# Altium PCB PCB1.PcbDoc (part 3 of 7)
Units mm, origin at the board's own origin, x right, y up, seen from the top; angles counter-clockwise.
Board outline 139.9 x 46.81 mm, 2 copper layers (Top Layer, Bottom Layer); 0 components, 100 nets, 100 pads, 0 vias.
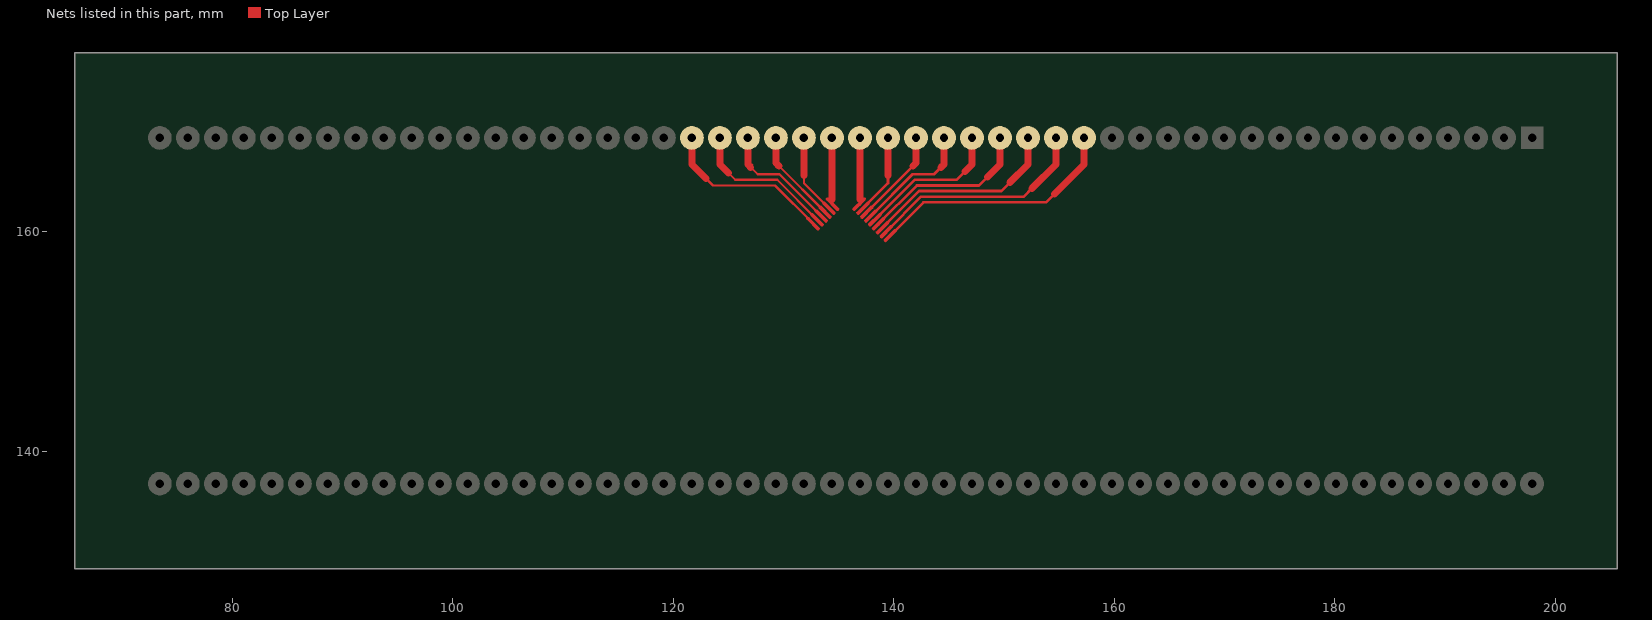
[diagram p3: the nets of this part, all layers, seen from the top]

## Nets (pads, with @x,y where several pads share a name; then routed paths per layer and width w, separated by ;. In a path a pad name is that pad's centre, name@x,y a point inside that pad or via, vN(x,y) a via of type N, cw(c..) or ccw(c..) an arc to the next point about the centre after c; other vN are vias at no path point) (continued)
$Net29: pad.1@121.687,168.455 | length 39.5
  Top Layer w0.03: 132.119,161.129 132.388,161.129 ; 132.121,161.114 132.403,161.114 ; 132.124,161.099 132.419,161.099 ; 132.132,161.084 132.434,161.084 ; 132.134,161.175 132.342,161.175 ; 132.144,161.068 132.449,161.068 ; 132.16,161.053 132.464,161.053 ; 132.16,161.206 132.312,161.206 ; 132.175,161.038 132.48,161.038 ; 132.177,161.221 132.297,161.221 ; 132.19,161.023 132.495,161.023 ; 132.2,161.236 132.274,161.236 ; 132.205,161.007 132.51,161.007 ; 132.22,160.992 132.525,160.992 ; 132.236,160.977 132.541,160.977 ; 132.251,160.962 132.556,160.962 ; 132.266,160.947 132.571,160.947 ; 132.281,160.931 132.586,160.931 ; 132.297,160.916 132.601,160.916 ; 132.312,160.901 132.617,160.901 ; 132.327,160.886 132.632,160.886 ; 132.327,161.19 132.144,161.19 ; 132.342,160.87 132.647,160.87 ; 132.358,160.855 132.662,160.855 ; 132.358,161.16 132.124,161.16 ; 132.373,160.84 132.678,160.84 ; 132.373,161.145 132.119,161.145 ; 132.388,160.825 132.693,160.825 ; 132.403,160.809 132.708,160.809 ; 132.419,160.794 132.723,160.794 ; 132.434,160.779 132.739,160.779 ; 132.449,160.764 132.754,160.764 ; 132.464,160.748 132.769,160.748 ; 132.48,160.733 132.782,160.733 ; 132.495,160.718 132.797,160.718 ; 132.51,160.703 132.812,160.703 ; 132.525,160.687 132.828,160.687 ; 132.541,160.672 132.843,160.672 ; 132.556,160.657 132.858,160.657 ; 132.571,160.642 132.873,160.642 ; 132.586,160.626 132.888,160.626 ; 132.601,160.611 132.904,160.611 ; 132.614,160.596 132.919,160.596 ; 132.629,160.581 132.934,160.581 ; 132.645,160.566 132.949,160.566 ; 132.66,160.55 132.965,160.55 ; 132.675,160.535 132.98,160.535 ; 132.69,160.52 132.995,160.52 ; 132.706,160.505 133.01,160.505 ; 132.721,160.489 133.026,160.489 ; 132.736,160.474 133.041,160.474 ; 132.751,160.459 133.056,160.459 ; 132.767,160.444 133.071,160.444 ; 132.782,160.428 133.087,160.428 ; 132.797,160.413 133.102,160.413 ; 132.812,160.398 133.117,160.398 ; 132.828,160.383 133.132,160.383 ; 132.843,160.367 133.148,160.367 ; 132.858,160.352 133.163,160.352 ; 132.873,160.337 133.178,160.337 ; 132.888,160.322 133.193,160.322 ; 132.904,160.306 133.209,160.306 ; 132.919,160.291 133.224,160.291 ; 132.934,160.276 133.239,160.276 ; 132.949,160.261 133.247,160.261 ; 132.965,160.245 133.252,160.245 ; 132.98,160.23 133.254,160.23 ; 132.995,160.215 133.254,160.215 ; 133.01,160.2 133.249,160.2 ; 133.026,160.185 133.242,160.185 ; 133.041,160.169 133.231,160.169 ; 133.056,160.154 133.216,160.154 ; 133.071,160.139 133.201,160.139 ; 133.181,160.124 133.087,160.124 ; 132.119,161.145 132.124,161.16 ; 132.119,161.145 132.116,161.127 132.124,161.094 132.132,161.081 133.074,160.134 133.087,160.124 ; 132.124,161.16 132.144,161.19 ; 132.144,161.19 132.172,161.218 132.203,161.239 132.218,161.244 132.236,161.246 132.269,161.239 132.284,161.231 132.297,161.221 ; 132.297,161.221 133.239,160.273 133.247,160.261 ; 133.087,160.124 133.102,160.116 133.135,160.108 133.153,160.111 133.168,160.116 133.198,160.136 133.226,160.164 133.247,160.195 133.252,160.21 133.254,160.228 133.247,160.261
  Top Layer w0.203: 122.957,164.772 123.592,164.137 129.226,164.137 132.685,160.677
  Top Layer w0.635: pad.1@121.687,168.455 121.687,166.042 122.957,164.772
$Net30: pad.1@124.227,168.455 | length 37.2
  Top Layer w0.03: 132.472,161.482 132.741,161.482 ; 132.474,161.467 132.756,161.467 ; 132.477,161.452 132.772,161.452 ; 132.485,161.437 132.787,161.437 ; 132.487,161.528 132.695,161.528 ; 132.497,161.421 132.802,161.421 ; 132.513,161.406 132.817,161.406 ; 132.513,161.559 132.665,161.559 ; 132.528,161.391 132.833,161.391 ; 132.53,161.574 132.65,161.574 ; 132.543,161.376 132.848,161.376 ; 132.553,161.589 132.627,161.589 ; 132.558,161.361 132.863,161.361 ; 132.574,161.345 132.878,161.345 ; 132.589,161.33 132.894,161.33 ; 132.604,161.315 132.909,161.315 ; 132.619,161.3 132.924,161.3 ; 132.634,161.284 132.939,161.284 ; 132.65,161.269 132.955,161.269 ; 132.665,161.254 132.97,161.254 ; 132.68,161.239 132.985,161.239 ; 132.68,161.543 132.497,161.543 ; 132.695,161.223 133,161.223 ; 132.711,161.208 133.015,161.208 ; 132.711,161.513 132.477,161.513 ; 132.726,161.193 133.031,161.193 ; 132.726,161.498 132.472,161.498 ; 132.741,161.178 133.046,161.178 ; 132.756,161.162 133.061,161.162 ; 132.772,161.147 133.076,161.147 ; 132.787,161.132 133.092,161.132 ; 132.802,161.117 133.107,161.117 ; 132.817,161.101 133.122,161.101 ; 132.833,161.086 133.135,161.086 ; 132.848,161.071 133.15,161.071 ; 132.863,161.056 133.165,161.056 ; 132.878,161.04 133.181,161.04 ; 132.894,161.025 133.196,161.025 ; 132.909,161.01 133.211,161.01 ; 132.924,160.995 133.226,160.995 ; 132.939,160.98 133.242,160.98 ; 132.955,160.964 133.257,160.964 ; 132.967,160.949 133.272,160.949 ; 132.982,160.934 133.287,160.934 ; 132.998,160.919 133.303,160.919 ; 133.013,160.903 133.318,160.903 ; 133.028,160.888 133.333,160.888 ; 133.043,160.873 133.348,160.873 ; 133.059,160.858 133.363,160.858 ; 133.074,160.842 133.379,160.842 ; 133.089,160.827 133.394,160.827 ; 133.104,160.812 133.409,160.812 ; 133.12,160.797 133.424,160.797 ; 133.135,160.781 133.44,160.781 ; 133.15,160.766 133.455,160.766 ; 133.165,160.751 133.47,160.751 ; 133.181,160.736 133.485,160.736 ; 133.196,160.72 133.501,160.72 ; 133.211,160.705 133.516,160.705 ; 133.226,160.69 133.531,160.69 ; 133.242,160.675 133.546,160.675 ; 133.257,160.659 133.562,160.659 ; 133.272,160.644 133.577,160.644 ; 133.287,160.629 133.592,160.629 ; 133.303,160.614 133.6,160.614 ; 133.318,160.599 133.605,160.599 ; 133.333,160.583 133.607,160.583 ; 133.348,160.568 133.607,160.568 ; 133.363,160.553 133.602,160.553 ; 133.379,160.538 133.595,160.538 ; 133.394,160.522 133.584,160.522 ; 133.409,160.507 133.569,160.507 ; 133.424,160.492 133.554,160.492 ; 133.534,160.477 133.44,160.477 ; 132.472,161.498 132.477,161.513 ; 132.472,161.498 132.469,161.48 132.477,161.447 132.485,161.434 133.427,160.487 133.44,160.477 ; 132.477,161.513 132.497,161.543 ; 132.497,161.543 132.525,161.571 132.556,161.592 132.571,161.597 132.589,161.599 132.622,161.592 132.637,161.584 132.65,161.574 ; 132.65,161.574 133.592,160.626 133.6,160.614 ; 133.44,160.477 133.455,160.469 133.488,160.461 133.506,160.464 133.521,160.469 133.551,160.489 133.579,160.517 133.6,160.548 133.605,160.563 133.607,160.581 133.6,160.614
  Top Layer w0.203: 124.989,165.28 125.624,164.645 129.426,164.645 133.038,161.03
  Top Layer w0.635: pad.1@124.227,168.455 124.227,166.042 124.989,165.28
$Net31: pad.1@126.767,168.455 | length 34.9
  Top Layer w0.03: 132.828,161.836 133.097,161.836 ; 132.83,161.82 133.112,161.82 ; 132.833,161.805 133.127,161.805 ; 132.84,161.79 133.142,161.79 ; 132.843,161.881 133.051,161.881 ; 132.853,161.775 133.158,161.775 ; 132.868,161.759 133.173,161.759 ; 132.868,161.912 133.021,161.912 ; 132.883,161.744 133.188,161.744 ; 132.886,161.927 133.005,161.927 ; 132.899,161.729 133.203,161.729 ; 132.909,161.942 132.982,161.942 ; 132.914,161.714 133.219,161.714 ; 132.929,161.698 133.234,161.698 ; 132.944,161.683 133.249,161.683 ; 132.96,161.668 133.264,161.668 ; 132.975,161.653 133.28,161.653 ; 132.99,161.637 133.295,161.637 ; 133.005,161.622 133.31,161.622 ; 133.021,161.607 133.325,161.607 ; 133.036,161.592 133.341,161.592 ; 133.036,161.896 132.853,161.896 ; 133.051,161.576 133.356,161.576 ; 133.066,161.561 133.371,161.561 ; 133.066,161.866 132.833,161.866 ; 133.082,161.546 133.386,161.546 ; 133.082,161.851 132.828,161.851 ; 133.097,161.531 133.402,161.531 ; 133.112,161.515 133.417,161.515 ; 133.127,161.5 133.432,161.5 ; 133.142,161.485 133.447,161.485 ; 133.158,161.47 133.463,161.47 ; 133.173,161.455 133.478,161.455 ; 133.188,161.439 133.49,161.439 ; 133.203,161.424 133.506,161.424 ; 133.219,161.409 133.521,161.409 ; 133.234,161.394 133.536,161.394 ; 133.249,161.378 133.551,161.378 ; 133.264,161.363 133.567,161.363 ; 133.28,161.348 133.582,161.348 ; 133.295,161.333 133.597,161.333 ; 133.31,161.317 133.612,161.317 ; 133.323,161.302 133.628,161.302 ; 133.338,161.287 133.643,161.287 ; 133.353,161.272 133.658,161.272 ; 133.369,161.256 133.673,161.256 ; 133.384,161.241 133.689,161.241 ; 133.399,161.226 133.704,161.226 ; 133.414,161.211 133.719,161.211 ; 133.43,161.195 133.734,161.195 ; 133.445,161.18 133.75,161.18 ; 133.46,161.165 133.765,161.165 ; 133.475,161.15 133.78,161.15 ; 133.49,161.134 133.795,161.134 ; 133.506,161.119 133.811,161.119 ; 133.521,161.104 133.826,161.104 ; 133.536,161.089 133.841,161.089 ; 133.551,161.074 133.856,161.074 ; 133.567,161.058 133.871,161.058 ; 133.582,161.043 133.887,161.043 ; 133.597,161.028 133.902,161.028 ; 133.612,161.013 133.917,161.013 ; 133.628,160.997 133.932,160.997 ; 133.643,160.982 133.948,160.982 ; 133.658,160.967 133.955,160.967 ; 133.673,160.952 133.96,160.952 ; 133.689,160.936 133.963,160.936 ; 133.704,160.921 133.963,160.921 ; 133.719,160.906 133.958,160.906 ; 133.734,160.891 133.95,160.891 ; 133.75,160.875 133.94,160.875 ; 133.765,160.86 133.925,160.86 ; 133.78,160.845 133.91,160.845 ; 133.889,160.83 133.795,160.83 ; 132.828,161.851 132.833,161.866 ; 132.828,161.851 132.825,161.833 132.833,161.8 132.84,161.787 133.783,160.84 133.795,160.83 ; 132.833,161.866 132.853,161.896 ; 132.853,161.896 132.881,161.924 132.911,161.945 132.927,161.95 132.944,161.952 132.977,161.945 132.993,161.937 133.005,161.927 ; 133.005,161.927 133.948,160.98 133.955,160.967 ; 133.795,160.83 133.811,160.822 133.844,160.814 133.861,160.817 133.877,160.822 133.907,160.842 133.935,160.87 133.955,160.901 133.96,160.916 133.963,160.934 133.955,160.967
  Top Layer w0.203: 127.021,165.788 127.656,165.153 129.625,165.153 133.394,161.383
  Top Layer w0.635: pad.1@126.767,168.455 126.767,166.042 127.021,165.788
$Net32: pad.1@129.307,168.455 | length 32.8
  Top Layer w0.03: 133.181,162.189 133.45,162.189 ; 133.183,162.173 133.465,162.173 ; 133.186,162.158 133.48,162.158 ; 133.193,162.143 133.496,162.143 ; 133.196,162.234 133.404,162.234 ; 133.206,162.128 133.511,162.128 ; 133.221,162.112 133.526,162.112 ; 133.221,162.265 133.374,162.265 ; 133.236,162.097 133.541,162.097 ; 133.239,162.28 133.358,162.28 ; 133.252,162.082 133.557,162.082 ; 133.262,162.295 133.336,162.295 ; 133.267,162.067 133.572,162.067 ; 133.282,162.051 133.587,162.051 ; 133.297,162.036 133.602,162.036 ; 133.313,162.021 133.617,162.021 ; 133.328,162.006 133.633,162.006 ; 133.343,161.99 133.648,161.99 ; 133.358,161.975 133.663,161.975 ; 133.374,161.96 133.678,161.96 ; 133.389,161.945 133.694,161.945 ; 133.389,162.25 133.206,162.25 ; 133.404,161.929 133.709,161.929 ; 133.419,161.914 133.724,161.914 ; 133.419,162.219 133.186,162.219 ; 133.435,161.899 133.739,161.899 ; 133.435,162.204 133.181,162.204 ; 133.45,161.884 133.755,161.884 ; 133.465,161.869 133.77,161.869 ; 133.48,161.853 133.785,161.853 ; 133.496,161.838 133.8,161.838 ; 133.511,161.823 133.816,161.823 ; 133.526,161.808 133.831,161.808 ; 133.541,161.792 133.844,161.792 ; 133.557,161.777 133.859,161.777 ; 133.572,161.762 133.874,161.762 ; 133.587,161.747 133.889,161.747 ; 133.602,161.731 133.904,161.731 ; 133.617,161.716 133.92,161.716 ; 133.633,161.701 133.935,161.701 ; 133.648,161.686 133.95,161.686 ; 133.663,161.67 133.965,161.67 ; 133.676,161.655 133.981,161.655 ; 133.691,161.64 133.996,161.64 ; 133.706,161.625 134.011,161.625 ; 133.722,161.609 134.026,161.609 ; 133.737,161.594 134.042,161.594 ; 133.752,161.579 134.057,161.579 ; 133.767,161.564 134.072,161.564 ; 133.783,161.548 134.087,161.548 ; 133.798,161.533 134.103,161.533 ; 133.813,161.518 134.118,161.518 ; 133.828,161.503 134.133,161.503 ; 133.844,161.488 134.148,161.488 ; 133.859,161.472 134.164,161.472 ; 133.874,161.457 134.179,161.457 ; 133.889,161.442 134.194,161.442 ; 133.904,161.427 134.209,161.427 ; 133.92,161.411 134.225,161.411 ; 133.935,161.396 134.24,161.396 ; 133.95,161.381 134.255,161.381 ; 133.965,161.366 134.27,161.366 ; 133.981,161.35 134.285,161.35 ; 133.996,161.335 134.301,161.335 ; 134.011,161.32 134.308,161.32 ; 134.026,161.305 134.313,161.305 ; 134.042,161.289 134.316,161.289 ; 134.057,161.274 134.316,161.274 ; 134.072,161.259 134.311,161.259 ; 134.087,161.244 134.303,161.244 ; 134.103,161.228 134.293,161.228 ; 134.118,161.213 134.278,161.213 ; 134.133,161.198 134.263,161.198 ; 134.242,161.183 134.148,161.183 ; 133.181,162.204 133.186,162.219 ; 133.181,162.204 133.178,162.186 133.186,162.153 133.193,162.14 134.136,161.193 134.148,161.183 ; 133.186,162.219 133.206,162.25 ; 133.206,162.25 133.234,162.277 133.264,162.298 133.28,162.303 133.297,162.305 133.33,162.298 133.346,162.29 133.358,162.28 ; 133.358,162.28 134.301,161.333 134.308,161.32 ; 134.148,161.183 134.164,161.175 134.197,161.167 134.214,161.17 134.23,161.175 134.26,161.195 134.288,161.223 134.308,161.254 134.313,161.269 134.316,161.287 134.308,161.32
  Top Layer w0.203: 129.307,166.179 129.564,165.92 133.747,161.736
  Top Layer w0.635: pad.1@129.307,168.455 129.307,166.179 129.564,165.92
$Net33: pad.1@131.847,168.455 | length 31.2
  Top Layer w0.03: 133.534,162.542 133.803,162.542 ; 133.536,162.526 133.818,162.526 ; 133.539,162.511 133.833,162.511 ; 133.546,162.496 133.849,162.496 ; 133.549,162.587 133.757,162.587 ; 133.559,162.481 133.864,162.481 ; 133.574,162.465 133.879,162.465 ; 133.574,162.618 133.727,162.618 ; 133.59,162.45 133.894,162.45 ; 133.592,162.633 133.711,162.633 ; 133.605,162.435 133.91,162.435 ; 133.615,162.648 133.689,162.648 ; 133.62,162.42 133.925,162.42 ; 133.635,162.404 133.94,162.404 ; 133.65,162.389 133.955,162.389 ; 133.666,162.374 133.971,162.374 ; 133.681,162.359 133.986,162.359 ; 133.696,162.344 134.001,162.344 ; 133.711,162.328 134.016,162.328 ; 133.727,162.313 134.031,162.313 ; 133.742,162.298 134.047,162.298 ; 133.742,162.603 133.559,162.603 ; 133.757,162.283 134.062,162.283 ; 133.772,162.267 134.077,162.267 ; 133.772,162.572 133.539,162.572 ; 133.788,162.252 134.092,162.252 ; 133.788,162.557 133.534,162.557 ; 133.803,162.237 134.108,162.237 ; 133.818,162.222 134.123,162.222 ; 133.833,162.206 134.138,162.206 ; 133.849,162.191 134.153,162.191 ; 133.864,162.176 134.169,162.176 ; 133.879,162.161 134.184,162.161 ; 133.894,162.145 134.197,162.145 ; 133.91,162.13 134.212,162.13 ; 133.925,162.115 134.227,162.115 ; 133.94,162.1 134.242,162.1 ; 133.955,162.084 134.258,162.084 ; 133.971,162.069 134.273,162.069 ; 133.986,162.054 134.288,162.054 ; 134.001,162.039 134.303,162.039 ; 134.016,162.023 134.319,162.023 ; 134.029,162.008 134.334,162.008 ; 134.044,161.993 134.349,161.993 ; 134.059,161.978 134.364,161.978 ; 134.075,161.963 134.379,161.963 ; 134.09,161.947 134.395,161.947 ; 134.105,161.932 134.41,161.932 ; 134.12,161.917 134.425,161.917 ; 134.136,161.902 134.44,161.902 ; 134.151,161.886 134.456,161.886 ; 134.166,161.871 134.471,161.871 ; 134.181,161.856 134.486,161.856 ; 134.197,161.841 134.501,161.841 ; 134.212,161.825 134.517,161.825 ; 134.227,161.81 134.532,161.81 ; 134.242,161.795 134.547,161.795 ; 134.258,161.78 134.562,161.78 ; 134.273,161.764 134.578,161.764 ; 134.288,161.749 134.593,161.749 ; 134.303,161.734 134.608,161.734 ; 134.319,161.719 134.623,161.719 ; 134.334,161.703 134.639,161.703 ; 134.349,161.688 134.654,161.688 ; 134.364,161.673 134.661,161.673 ; 134.379,161.658 134.666,161.658 ; 134.395,161.642 134.669,161.642 ; 134.41,161.627 134.669,161.627 ; 134.425,161.612 134.664,161.612 ; 134.44,161.597 134.656,161.597 ; 134.456,161.582 134.646,161.582 ; 134.471,161.566 134.631,161.566 ; 134.486,161.551 134.616,161.551 ; 134.595,161.536 134.501,161.536 ; 133.534,162.557 133.539,162.572 ; 133.534,162.557 133.531,162.539 133.539,162.506 133.546,162.493 134.489,161.546 134.501,161.536 ; 133.539,162.572 133.559,162.603 ; 133.559,162.603 133.587,162.631 133.617,162.651 133.633,162.656 133.65,162.658 133.684,162.651 133.699,162.643 133.711,162.633 ; 133.711,162.633 134.654,161.686 134.661,161.673 ; 134.501,161.536 134.517,161.528 134.55,161.521 134.567,161.523 134.583,161.528 134.613,161.548 134.641,161.576 134.661,161.607 134.666,161.622 134.669,161.64 134.661,161.673
  Top Layer w0.203: 131.847,165.026 131.847,164.345 134.1,162.09
  Top Layer w0.635: 131.847,165.026 pad.1@131.847,168.455
$Net34: pad.1@134.387,168.455 | length 30
  Top Layer w0.03: 133.887,162.897 134.156,162.897 ; 133.889,162.882 134.171,162.882 ; 133.892,162.867 134.186,162.867 ; 133.899,162.852 134.202,162.852 ; 133.902,162.943 134.11,162.943 ; 133.912,162.836 134.217,162.836 ; 133.927,162.821 134.232,162.821 ; 133.927,162.973 134.08,162.973 ; 133.943,162.806 134.247,162.806 ; 133.945,162.989 134.065,162.989 ; 133.958,162.791 134.263,162.791 ; 133.968,163.004 134.042,163.004 ; 133.973,162.775 134.278,162.775 ; 133.988,162.76 134.293,162.76 ; 134.004,162.745 134.308,162.745 ; 134.019,162.73 134.324,162.73 ; 134.034,162.714 134.339,162.714 ; 134.049,162.699 134.354,162.699 ; 134.065,162.684 134.369,162.684 ; 134.08,162.669 134.385,162.669 ; 134.095,162.653 134.4,162.653 ; 134.095,162.958 133.912,162.958 ; 134.11,162.638 134.415,162.638 ; 134.125,162.623 134.43,162.623 ; 134.125,162.928 133.892,162.928 ; 134.141,162.608 134.446,162.608 ; 134.141,162.912 133.887,162.912 ; 134.156,162.592 134.461,162.592 ; 134.171,162.577 134.476,162.577 ; 134.186,162.562 134.491,162.562 ; 134.202,162.547 134.506,162.547 ; 134.217,162.531 134.522,162.531 ; 134.232,162.516 134.537,162.516 ; 134.247,162.501 134.55,162.501 ; 134.263,162.486 134.565,162.486 ; 134.278,162.471 134.58,162.471 ; 134.293,162.455 134.595,162.455 ; 134.308,162.44 134.611,162.44 ; 134.324,162.425 134.626,162.425 ; 134.339,162.41 134.641,162.41 ; 134.354,162.394 134.656,162.394 ; 134.369,162.379 134.672,162.379 ; 134.382,162.364 134.687,162.364 ; 134.397,162.349 134.702,162.349 ; 134.412,162.333 134.717,162.333 ; 134.428,162.318 134.733,162.318 ; 134.443,162.303 134.748,162.303 ; 134.458,162.288 134.763,162.288 ; 134.473,162.272 134.778,162.272 ; 134.489,162.257 134.793,162.257 ; 134.504,162.242 134.809,162.242 ; 134.519,162.227 134.824,162.227 ; 134.534,162.211 134.839,162.211 ; 134.55,162.196 134.854,162.196 ; 134.565,162.181 134.87,162.181 ; 134.58,162.166 134.885,162.166 ; 134.595,162.15 134.9,162.15 ; 134.611,162.135 134.915,162.135 ; 134.626,162.12 134.931,162.12 ; 134.641,162.105 134.946,162.105 ; 134.656,162.09 134.961,162.09 ; 134.672,162.074 134.976,162.074 ; 134.687,162.059 134.992,162.059 ; 134.702,162.044 135.007,162.044 ; 134.717,162.029 135.014,162.029 ; 134.733,162.013 135.02,162.013 ; 134.748,161.998 135.022,161.998 ; 134.763,161.983 135.022,161.983 ; 134.778,161.968 135.017,161.968 ; 134.793,161.952 135.009,161.952 ; 134.809,161.937 134.999,161.937 ; 134.824,161.922 134.984,161.922 ; 134.839,161.907 134.969,161.907 ; 134.948,161.891 134.854,161.891 ; 133.887,162.912 133.892,162.928 ; 133.887,162.912 133.884,162.895 133.892,162.862 133.899,162.849 134.842,161.902 134.854,161.891 ; 133.892,162.928 133.912,162.958 ; 133.912,162.958 133.94,162.986 133.971,163.006 133.986,163.012 134.004,163.014 134.037,163.006 134.052,162.999 134.065,162.989 ; 134.065,162.989 135.007,162.041 135.014,162.029 ; 134.854,161.891 134.87,161.884 134.903,161.876 134.92,161.879 134.936,161.884 134.966,161.904 134.994,161.932 135.014,161.963 135.02,161.978 135.022,161.996 135.014,162.029
  Top Layer w0.203: 134.387,162.867 134.387,162.511 134.453,162.445
  Top Layer w0.635: 134.387,162.867 pad.1@134.387,168.455
$Net35: pad.1@136.927,168.455 | length 29.9
  Top Layer w0.03: 136.292,161.983 136.549,161.983 ; 136.292,161.998 136.564,161.998 ; 136.295,162.013 136.579,162.013 ; 136.297,161.968 136.533,161.968 ; 136.305,161.952 136.518,161.952 ; 136.315,161.937 136.503,161.937 ; 136.32,162.059 136.625,162.059 ; 136.328,161.922 136.488,161.922 ; 136.335,162.074 136.64,162.074 ; 136.343,161.907 136.472,161.907 ; 136.351,162.09 136.655,162.09 ; 136.366,161.891 136.455,161.891 ; 136.366,162.105 136.671,162.105 ; 136.381,162.12 136.686,162.12 ; 136.396,162.135 136.701,162.135 ; 136.411,162.15 136.716,162.15 ; 136.427,162.166 136.732,162.166 ; 136.442,162.181 136.747,162.181 ; 136.457,162.196 136.762,162.196 ; 136.472,162.211 136.777,162.211 ; 136.488,162.227 136.792,162.227 ; 136.503,162.242 136.808,162.242 ; 136.518,162.257 136.823,162.257 ; 136.533,162.272 136.838,162.272 ; 136.549,162.288 136.853,162.288 ; 136.564,162.303 136.869,162.303 ; 136.579,162.318 136.884,162.318 ; 136.594,162.029 136.297,162.029 ; 136.594,162.333 136.899,162.333 ; 136.61,162.044 136.305,162.044 ; 136.61,162.349 136.914,162.349 ; 136.625,162.364 136.932,162.364 ; 136.64,162.379 136.947,162.379 ; 136.655,162.394 136.963,162.394 ; 136.671,162.41 136.978,162.41 ; 136.686,162.425 136.993,162.425 ; 136.701,162.44 137.008,162.44 ; 136.716,162.455 137.024,162.455 ; 136.732,162.471 137.039,162.471 ; 136.747,162.486 137.054,162.486 ; 136.762,162.501 137.069,162.501 ; 136.777,162.516 137.085,162.516 ; 136.795,162.531 137.1,162.531 ; 136.81,162.547 137.115,162.547 ; 136.825,162.562 137.13,162.562 ; 136.841,162.577 137.146,162.577 ; 136.856,162.592 137.161,162.592 ; 136.871,162.608 137.176,162.608 ; 136.886,162.623 137.191,162.623 ; 136.902,162.638 137.206,162.638 ; 136.917,162.653 137.222,162.653 ; 136.932,162.669 137.237,162.669 ; 136.947,162.684 137.252,162.684 ; 136.963,162.699 137.267,162.699 ; 136.978,162.714 137.283,162.714 ; 136.993,162.73 137.298,162.73 ; 137.008,162.745 137.313,162.745 ; 137.024,162.76 137.328,162.76 ; 137.039,162.775 137.344,162.775 ; 137.054,162.791 137.359,162.791 ; 137.069,162.806 137.374,162.806 ; 137.085,162.821 137.389,162.821 ; 137.1,162.836 137.405,162.836 ; 137.115,162.852 137.415,162.852 ; 137.13,162.867 137.422,162.867 ; 137.146,162.882 137.425,162.882 ; 137.161,162.897 137.427,162.897 ; 137.176,162.912 137.425,162.912 ; 137.191,162.928 137.42,162.928 ; 137.206,162.943 137.41,162.943 ; 137.222,162.958 137.4,162.958 ; 137.237,162.973 137.384,162.973 ; 137.252,162.989 137.369,162.989 ; 137.273,163.004 137.346,163.004 ; 136.297,162.029 136.305,162.044 ; 136.297,162.029 136.29,161.996 136.292,161.978 136.297,161.963 136.317,161.932 136.345,161.904 136.376,161.884 136.391,161.879 136.409,161.876 136.442,161.884 136.455,161.891 ; 136.305,162.044 136.315,162.056 137.262,162.999 137.275,163.006 137.308,163.014 137.326,163.012 137.341,163.006 137.372,162.986 137.4,162.958 ; 136.455,161.891 137.402,162.834 137.412,162.846 137.42,162.862 137.427,162.895 137.425,162.912 ; 137.4,162.958 137.42,162.928 ; 137.42,162.928 137.425,162.912
  Top Layer w0.203: 136.859,162.445 136.927,162.511 136.927,162.867
  Top Layer w0.635: 136.927,162.867 pad.1@136.927,168.455
$Net36: pad.1@139.467,168.455 | length 31.2
  Top Layer w0.03: 136.645,161.627 136.902,161.627 ; 136.645,161.642 136.917,161.642 ; 136.648,161.658 136.932,161.658 ; 136.65,161.612 136.886,161.612 ; 136.658,161.597 136.871,161.597 ; 136.668,161.582 136.856,161.582 ; 136.673,161.703 136.978,161.703 ; 136.681,161.566 136.841,161.566 ; 136.688,161.719 136.993,161.719 ; 136.696,161.551 136.825,161.551 ; 136.704,161.734 137.008,161.734 ; 136.719,161.536 136.808,161.536 ; 136.719,161.749 137.024,161.749 ; 136.734,161.764 137.039,161.764 ; 136.749,161.78 137.054,161.78 ; 136.765,161.795 137.069,161.795 ; 136.78,161.81 137.085,161.81 ; 136.795,161.825 137.1,161.825 ; 136.81,161.841 137.115,161.841 ; 136.825,161.856 137.13,161.856 ; 136.841,161.871 137.146,161.871 ; 136.856,161.886 137.161,161.886 ; 136.871,161.902 137.176,161.902 ; 136.886,161.917 137.191,161.917 ; 136.902,161.932 137.206,161.932 ; 136.917,161.947 137.222,161.947 ; 136.932,161.963 137.237,161.963 ; 136.947,161.673 136.65,161.673 ; 136.947,161.978 137.252,161.978 ; 136.963,161.688 136.658,161.688 ; 136.963,161.993 137.267,161.993 ; 136.978,162.008 137.285,162.008 ; 136.993,162.023 137.3,162.023 ; 137.008,162.039 137.316,162.039 ; 137.024,162.054 137.331,162.054 ; 137.039,162.069 137.346,162.069 ; 137.054,162.084 137.361,162.084 ; 137.069,162.1 137.377,162.1 ; 137.085,162.115 137.392,162.115 ; 137.1,162.13 137.407,162.13 ; 137.115,162.145 137.422,162.145 ; 137.13,162.161 137.438,162.161 ; 137.148,162.176 137.453,162.176 ; 137.163,162.191 137.468,162.191 ; 137.179,162.206 137.483,162.206 ; 137.194,162.222 137.499,162.222 ; 137.209,162.237 137.514,162.237 ; 137.224,162.252 137.529,162.252 ; 137.24,162.267 137.544,162.267 ; 137.255,162.283 137.56,162.283 ; 137.27,162.298 137.575,162.298 ; 137.285,162.313 137.59,162.313 ; 137.3,162.328 137.605,162.328 ; 137.316,162.344 137.621,162.344 ; 137.331,162.359 137.636,162.359 ; 137.346,162.374 137.651,162.374 ; 137.361,162.389 137.666,162.389 ; 137.377,162.404 137.681,162.404 ; 137.392,162.42 137.697,162.42 ; 137.407,162.435 137.712,162.435 ; 137.422,162.45 137.727,162.45 ; 137.438,162.465 137.742,162.465 ; 137.453,162.481 137.758,162.481 ; 137.468,162.496 137.768,162.496 ; 137.483,162.511 137.775,162.511 ; 137.499,162.526 137.778,162.526 ; 137.514,162.542 137.781,162.542 ; 137.529,162.557 137.778,162.557 ; 137.544,162.572 137.773,162.572 ; 137.56,162.587 137.763,162.587 ; 137.575,162.603 137.753,162.603 ; 137.59,162.618 137.737,162.618 ; 137.605,162.633 137.722,162.633 ; 137.626,162.648 137.699,162.648 ; 136.65,161.673 136.658,161.688 ; 136.65,161.673 136.643,161.64 136.645,161.622 136.65,161.607 136.671,161.576 136.698,161.548 136.729,161.528 136.744,161.523 136.762,161.521 136.795,161.528 136.808,161.536 ; 136.658,161.688 136.668,161.701 137.615,162.643 137.628,162.651 137.661,162.658 137.679,162.656 137.694,162.651 137.725,162.631 137.753,162.603 ; 136.808,161.536 137.755,162.478 137.765,162.491 137.773,162.506 137.781,162.539 137.778,162.557 ; 137.753,162.603 137.773,162.572 ; 137.773,162.572 137.778,162.557
  Top Layer w0.241: 137.212,162.09 139.467,164.345 139.467,165.026
  Top Layer w0.635: 139.467,165.026 pad.1@139.467,168.455
$Net37: pad.1@142.007,168.455 | length 38.4
  Top Layer w0.03: 136.998,161.274 137.255,161.274 ; 136.998,161.289 137.27,161.289 ; 137.001,161.305 137.285,161.305 ; 137.003,161.259 137.24,161.259 ; 137.011,161.244 137.224,161.244 ; 137.021,161.228 137.209,161.228 ; 137.026,161.35 137.331,161.35 ; 137.034,161.213 137.194,161.213 ; 137.041,161.366 137.346,161.366 ; 137.049,161.198 137.179,161.198 ; 137.057,161.381 137.361,161.381 ; 137.072,161.183 137.161,161.183 ; 137.072,161.396 137.377,161.396 ; 137.087,161.411 137.392,161.411 ; 137.102,161.427 137.407,161.427 ; 137.118,161.442 137.422,161.442 ; 137.133,161.457 137.438,161.457 ; 137.148,161.472 137.453,161.472 ; 137.163,161.488 137.468,161.488 ; 137.179,161.503 137.483,161.503 ; 137.194,161.518 137.499,161.518 ; 137.209,161.533 137.514,161.533 ; 137.224,161.548 137.529,161.548 ; 137.24,161.564 137.544,161.564 ; 137.255,161.579 137.56,161.579 ; 137.27,161.594 137.575,161.594 ; 137.285,161.609 137.59,161.609 ; 137.3,161.32 137.003,161.32 ; 137.3,161.625 137.605,161.625 ; 137.316,161.335 137.011,161.335 ; 137.316,161.64 137.621,161.64 ; 137.331,161.655 137.638,161.655 ; 137.346,161.67 137.654,161.67 ; 137.361,161.686 137.669,161.686 ; 137.377,161.701 137.684,161.701 ; 137.392,161.716 137.699,161.716 ; 137.407,161.731 137.714,161.731 ; 137.422,161.747 137.73,161.747 ; 137.438,161.762 137.745,161.762 ; 137.453,161.777 137.76,161.777 ; 137.468,161.792 137.775,161.792 ; 137.483,161.808 137.791,161.808 ; 137.501,161.823 137.806,161.823 ; 137.516,161.838 137.821,161.838 ; 137.532,161.853 137.836,161.853 ; 137.547,161.869 137.852,161.869 ; 137.562,161.884 137.867,161.884 ; 137.577,161.899 137.882,161.899 ; 137.593,161.914 137.897,161.914 ; 137.608,161.929 137.913,161.929 ; 137.623,161.945 137.928,161.945 ; 137.638,161.96 137.943,161.96 ; 137.654,161.975 137.958,161.975 ; 137.669,161.99 137.974,161.99 ; 137.684,162.006 137.989,162.006 ; 137.699,162.021 138.004,162.021 ; 137.714,162.036 138.019,162.036 ; 137.73,162.051 138.035,162.051 ; 137.745,162.067 138.05,162.067 ; 137.76,162.082 138.065,162.082 ; 137.775,162.097 138.08,162.097 ; 137.791,162.112 138.095,162.112 ; 137.806,162.128 138.111,162.128 ; 137.821,162.143 138.121,162.143 ; 137.836,162.158 138.129,162.158 ; 137.852,162.173 138.131,162.173 ; 137.867,162.189 138.134,162.189 ; 137.882,162.204 138.131,162.204 ; 137.897,162.219 138.126,162.219 ; 137.913,162.234 138.116,162.234 ; 137.928,162.25 138.106,162.25 ; 137.943,162.265 138.09,162.265 ; 137.958,162.28 138.075,162.28 ; 137.979,162.295 138.052,162.295 ; 137.003,161.32 137.011,161.335 ; 137.003,161.32 136.996,161.287 136.998,161.269 137.003,161.254 137.024,161.223 137.052,161.195 137.082,161.175 137.097,161.17 137.115,161.167 137.148,161.175 137.161,161.183 ; 137.011,161.335 137.021,161.348 137.968,162.29 137.981,162.298 138.014,162.305 138.032,162.303 138.047,162.298 138.078,162.277 138.106,162.25 ; 137.161,161.183 138.108,162.125 138.118,162.138 138.126,162.153 138.134,162.186 138.131,162.204 ; 138.106,162.25 138.126,162.219 ; 138.126,162.219 138.131,162.204
  Top Layer w0.203: 137.565,161.736 141.748,165.92
  Top Layer w0.241: 137.565,161.736 141.748,165.92
  Top Layer w0.635: 141.748,165.92 142.007,166.179 pad.1@142.007,168.455
$Net38: pad.1@144.547,168.455 | length 35.8
  Top Layer w0.03: 137.351,160.921 137.608,160.921 ; 137.351,160.936 137.623,160.936 ; 137.354,160.952 137.638,160.952 ; 137.356,160.906 137.593,160.906 ; 137.364,160.891 137.577,160.891 ; 137.374,160.875 137.562,160.875 ; 137.379,160.997 137.684,160.997 ; 137.387,160.86 137.547,160.86 ; 137.394,161.013 137.699,161.013 ; 137.402,160.845 137.532,160.845 ; 137.41,161.028 137.714,161.028 ; 137.425,160.83 137.514,160.83 ; 137.425,161.043 137.73,161.043 ; 137.44,161.058 137.745,161.058 ; 137.455,161.074 137.76,161.074 ; 137.471,161.089 137.775,161.089 ; 137.486,161.104 137.791,161.104 ; 137.501,161.119 137.806,161.119 ; 137.516,161.134 137.821,161.134 ; 137.532,161.15 137.836,161.15 ; 137.547,161.165 137.852,161.165 ; 137.562,161.18 137.867,161.18 ; 137.577,161.195 137.882,161.195 ; 137.593,161.211 137.897,161.211 ; 137.608,161.226 137.913,161.226 ; 137.623,161.241 137.928,161.241 ; 137.638,161.256 137.943,161.256 ; 137.654,160.967 137.356,160.967 ; 137.654,161.272 137.958,161.272 ; 137.669,160.982 137.364,160.982 ; 137.669,161.287 137.974,161.287 ; 137.684,161.302 137.991,161.302 ; 137.699,161.317 138.007,161.317 ; 137.714,161.333 138.022,161.333 ; 137.73,161.348 138.037,161.348 ; 137.745,161.363 138.052,161.363 ; 137.76,161.378 138.068,161.378 ; 137.775,161.394 138.083,161.394 ; 137.791,161.409 138.098,161.409 ; 137.806,161.424 138.113,161.424 ; 137.821,161.439 138.129,161.439 ; 137.836,161.455 138.144,161.455 ; 137.854,161.47 138.159,161.47 ; 137.869,161.485 138.174,161.485 ; 137.885,161.5 138.189,161.5 ; 137.9,161.515 138.205,161.515 ; 137.915,161.531 138.22,161.531 ; 137.93,161.546 138.235,161.546 ; 137.946,161.561 138.25,161.561 ; 137.961,161.576 138.266,161.576 ; 137.976,161.592 138.281,161.592 ; 137.991,161.607 138.296,161.607 ; 138.007,161.622 138.311,161.622 ; 138.022,161.637 138.327,161.637 ; 138.037,161.653 138.342,161.653 ; 138.052,161.668 138.357,161.668 ; 138.068,161.683 138.372,161.683 ; 138.083,161.698 138.388,161.698 ; 138.098,161.714 138.403,161.714 ; 138.113,161.729 138.418,161.729 ; 138.129,161.744 138.433,161.744 ; 138.144,161.759 138.449,161.759 ; 138.159,161.775 138.464,161.775 ; 138.174,161.79 138.474,161.79 ; 138.189,161.805 138.482,161.805 ; 138.205,161.82 138.484,161.82 ; 138.22,161.836 138.487,161.836 ; 138.235,161.851 138.484,161.851 ; 138.25,161.866 138.479,161.866 ; 138.266,161.881 138.469,161.881 ; 138.281,161.896 138.459,161.896 ; 138.296,161.912 138.443,161.912 ; 138.311,161.927 138.428,161.927 ; 138.332,161.942 138.405,161.942 ; 137.356,160.967 137.364,160.982 ; 137.356,160.967 137.349,160.934 137.351,160.916 137.356,160.901 137.377,160.87 137.405,160.842 137.435,160.822 137.45,160.817 137.468,160.814 137.501,160.822 137.514,160.83 ; 137.364,160.982 137.374,160.995 138.322,161.937 138.334,161.945 138.367,161.952 138.385,161.95 138.4,161.945 138.431,161.924 138.459,161.896 ; 137.514,160.83 138.461,161.772 138.471,161.785 138.479,161.8 138.487,161.833 138.484,161.851 ; 138.459,161.896 138.479,161.866 ; 138.479,161.866 138.484,161.851
  Top Layer w0.203: 143.658,165.153 144.293,165.788
  Top Layer w0.241: 137.918,161.383 141.687,165.153 143.658,165.153 144.293,165.788
  Top Layer w0.635: 144.293,165.788 144.547,166.042 pad.1@144.547,168.455
$Net39: pad.1@147.087,168.455 | length 37.2
  Top Layer w0.03: 137.707,160.568 137.963,160.568 ; 137.707,160.583 137.979,160.583 ; 137.709,160.599 137.994,160.599 ; 137.712,160.553 137.948,160.553 ; 137.72,160.538 137.933,160.538 ; 137.73,160.522 137.918,160.522 ; 137.735,160.644 138.04,160.644 ; 137.742,160.507 137.902,160.507 ; 137.75,160.659 138.055,160.659 ; 137.758,160.492 137.887,160.492 ; 137.765,160.675 138.07,160.675 ; 137.781,160.477 137.869,160.477 ; 137.781,160.69 138.085,160.69 ; 137.796,160.705 138.101,160.705 ; 137.811,160.72 138.116,160.72 ; 137.826,160.736 138.131,160.736 ; 137.841,160.751 138.146,160.751 ; 137.857,160.766 138.162,160.766 ; 137.872,160.781 138.177,160.781 ; 137.887,160.797 138.192,160.797 ; 137.902,160.812 138.207,160.812 ; 137.918,160.827 138.222,160.827 ; 137.933,160.842 138.238,160.842 ; 137.948,160.858 138.253,160.858 ; 137.963,160.873 138.268,160.873 ; 137.979,160.888 138.283,160.888 ; 137.994,160.903 138.299,160.903 ; 138.009,160.614 137.712,160.614 ; 138.009,160.919 138.314,160.919 ; 138.024,160.629 137.72,160.629 ; 138.024,160.934 138.329,160.934 ; 138.04,160.949 138.347,160.949 ; 138.055,160.964 138.362,160.964 ; 138.07,160.98 138.377,160.98 ; 138.085,160.995 138.393,160.995 ; 138.101,161.01 138.408,161.01 ; 138.116,161.025 138.423,161.025 ; 138.131,161.04 138.438,161.04 ; 138.146,161.056 138.454,161.056 ; 138.162,161.071 138.469,161.071 ; 138.177,161.086 138.484,161.086 ; 138.192,161.101 138.499,161.101 ; 138.21,161.117 138.515,161.117 ; 138.225,161.132 138.53,161.132 ; 138.24,161.147 138.545,161.147 ; 138.256,161.162 138.56,161.162 ; 138.271,161.178 138.576,161.178 ; 138.286,161.193 138.591,161.193 ; 138.301,161.208 138.606,161.208 ; 138.316,161.223 138.621,161.223 ; 138.332,161.239 138.637,161.239 ; 138.347,161.254 138.652,161.254 ; 138.362,161.269 138.667,161.269 ; 138.377,161.284 138.682,161.284 ; 138.393,161.3 138.697,161.3 ; 138.408,161.315 138.713,161.315 ; 138.423,161.33 138.728,161.33 ; 138.438,161.345 138.743,161.345 ; 138.454,161.361 138.758,161.361 ; 138.469,161.376 138.774,161.376 ; 138.484,161.391 138.789,161.391 ; 138.499,161.406 138.804,161.406 ; 138.515,161.421 138.819,161.421 ; 138.53,161.437 138.83,161.437 ; 138.545,161.452 138.837,161.452 ; 138.56,161.467 138.84,161.467 ; 138.576,161.482 138.842,161.482 ; 138.591,161.498 138.84,161.498 ; 138.606,161.513 138.835,161.513 ; 138.621,161.528 138.824,161.528 ; 138.637,161.543 138.814,161.543 ; 138.652,161.559 138.799,161.559 ; 138.667,161.574 138.784,161.574 ; 138.687,161.589 138.761,161.589 ; 137.712,160.614 137.72,160.629 ; 137.712,160.614 137.704,160.581 137.707,160.563 137.712,160.548 137.732,160.517 137.76,160.489 137.791,160.469 137.806,160.464 137.824,160.461 137.857,160.469 137.869,160.477 ; 137.72,160.629 137.73,160.642 138.677,161.584 138.69,161.592 138.723,161.599 138.741,161.597 138.756,161.592 138.786,161.571 138.814,161.543 ; 137.869,160.477 138.817,161.419 138.827,161.432 138.835,161.447 138.842,161.48 138.84,161.498 ; 138.814,161.543 138.835,161.513 ; 138.835,161.513 138.84,161.498
  Top Layer w0.241: 138.273,161.03 141.885,164.645 145.69,164.645 146.452,165.407
  Top Layer w0.635: 146.452,165.407 147.087,166.042 pad.1@147.087,168.455
$Net40: pad.1@149.627,168.455 | length 39.5
  Top Layer w0.03: 138.06,160.215 138.316,160.215 ; 138.06,160.23 138.332,160.23 ; 138.062,160.245 138.347,160.245 ; 138.065,160.2 138.301,160.2 ; 138.073,160.185 138.286,160.185 ; 138.083,160.169 138.271,160.169 ; 138.088,160.291 138.393,160.291 ; 138.095,160.154 138.256,160.154 ; 138.103,160.306 138.408,160.306 ; 138.111,160.139 138.24,160.139 ; 138.118,160.322 138.423,160.322 ; 138.134,160.124 138.222,160.124 ; 138.134,160.337 138.438,160.337 ; 138.149,160.352 138.454,160.352 ; 138.164,160.367 138.469,160.367 ; 138.179,160.383 138.484,160.383 ; 138.195,160.398 138.499,160.398 ; 138.21,160.413 138.515,160.413 ; 138.225,160.428 138.53,160.428 ; 138.24,160.444 138.545,160.444 ; 138.256,160.459 138.56,160.459 ; 138.271,160.474 138.576,160.474 ; 138.286,160.489 138.591,160.489 ; 138.301,160.505 138.606,160.505 ; 138.316,160.52 138.621,160.52 ; 138.332,160.535 138.637,160.535 ; 138.347,160.55 138.652,160.55 ; 138.362,160.261 138.065,160.261 ; 138.362,160.566 138.667,160.566 ; 138.377,160.276 138.073,160.276 ; 138.377,160.581 138.682,160.581 ; 138.393,160.596 138.7,160.596 ; 138.408,160.611 138.715,160.611 ; 138.423,160.626 138.73,160.626 ; 138.438,160.642 138.746,160.642 ; 138.454,160.657 138.761,160.657 ; 138.469,160.672 138.776,160.672 ; 138.484,160.687 138.791,160.687 ; 138.499,160.703 138.807,160.703 ; 138.515,160.718 138.822,160.718 ; 138.53,160.733 138.837,160.733 ; 138.545,160.748 138.852,160.748 ; 138.563,160.764 138.868,160.764 ; 138.578,160.779 138.883,160.779 ; 138.593,160.794 138.898,160.794 ; 138.609,160.809 138.913,160.809 ; 138.624,160.825 138.929,160.825 ; 138.639,160.84 138.944,160.84 ; 138.654,160.855 138.959,160.855 ; 138.67,160.87 138.974,160.87 ; 138.685,160.886 138.99,160.886 ; 138.7,160.901 139.005,160.901 ; 138.715,160.916 139.02,160.916 ; 138.73,160.931 139.035,160.931 ; 138.746,160.947 139.051,160.947 ; 138.761,160.962 139.066,160.962 ; 138.776,160.977 139.081,160.977 ; 138.791,160.992 139.096,160.992 ; 138.807,161.007 139.111,161.007 ; 138.822,161.023 139.127,161.023 ; 138.837,161.038 139.142,161.038 ; 138.852,161.053 139.157,161.053 ; 138.868,161.068 139.172,161.068 ; 138.883,161.084 139.183,161.084 ; 138.898,161.099 139.19,161.099 ; 138.913,161.114 139.193,161.114 ; 138.929,161.129 139.195,161.129 ; 138.944,161.145 139.193,161.145 ; 138.959,161.16 139.188,161.16 ; 138.974,161.175 139.178,161.175 ; 138.99,161.19 139.167,161.19 ; 139.005,161.206 139.152,161.206 ; 139.02,161.221 139.137,161.221 ; 139.04,161.236 139.114,161.236 ; 138.065,160.261 138.073,160.276 ; 138.065,160.261 138.057,160.228 138.06,160.21 138.065,160.195 138.085,160.164 138.113,160.136 138.144,160.116 138.159,160.111 138.177,160.108 138.21,160.116 138.222,160.124 ; 138.073,160.276 138.083,160.289 139.03,161.231 139.043,161.239 139.076,161.246 139.094,161.244 139.109,161.239 139.139,161.218 139.167,161.19 ; 138.222,160.124 139.17,161.066 139.18,161.079 139.188,161.094 139.195,161.127 139.193,161.145 ; 139.167,161.19 139.188,161.16 ; 139.188,161.16 139.193,161.145
  Top Layer w0.241: 138.626,160.677 142.086,164.137 147.722,164.137 148.484,164.899
  Top Layer w0.635: 148.484,164.899 149.627,166.042 pad.1@149.627,168.455
$Net41: pad.1@152.167,168.455 | length 41.9
  Top Layer w0.03: 138.413,159.859 138.67,159.859 ; 138.413,159.875 138.685,159.875 ; 138.416,159.89 138.7,159.89 ; 138.418,159.844 138.654,159.844 ; 138.426,159.829 138.639,159.829 ; 138.436,159.814 138.624,159.814 ; 138.441,159.936 138.746,159.936 ; 138.449,159.798 138.609,159.798 ; 138.456,159.951 138.761,159.951 ; 138.464,159.783 138.593,159.783 ; 138.471,159.966 138.776,159.966 ; 138.487,159.768 138.576,159.768 ; 138.487,159.981 138.791,159.981 ; 138.502,159.997 138.807,159.997 ; 138.517,160.012 138.822,160.012 ; 138.532,160.027 138.837,160.027 ; 138.548,160.042 138.852,160.042 ; 138.563,160.058 138.868,160.058 ; 138.578,160.073 138.883,160.073 ; 138.593,160.088 138.898,160.088 ; 138.609,160.103 138.913,160.103 ; 138.624,160.118 138.929,160.118 ; 138.639,160.134 138.944,160.134 ; 138.654,160.149 138.959,160.149 ; 138.67,160.164 138.974,160.164 ; 138.685,160.179 138.99,160.179 ; 138.7,160.195 139.005,160.195 ; 138.715,159.905 138.418,159.905 ; 138.715,160.21 139.02,160.21 ; 138.73,159.92 138.426,159.92 ; 138.73,160.225 139.035,160.225 ; 138.746,160.24 139.053,160.24 ; 138.761,160.256 139.068,160.256 ; 138.776,160.271 139.084,160.271 ; 138.791,160.286 139.099,160.286 ; 138.807,160.301 139.114,160.301 ; 138.822,160.317 139.129,160.317 ; 138.837,160.332 139.145,160.332 ; 138.852,160.347 139.16,160.347 ; 138.868,160.362 139.175,160.362 ; 138.883,160.378 139.19,160.378 ; 138.898,160.393 139.205,160.393 ; 138.916,160.408 139.221,160.408 ; 138.931,160.423 139.236,160.423 ; 138.946,160.439 139.251,160.439 ; 138.962,160.454 139.266,160.454 ; 138.977,160.469 139.282,160.469 ; 138.992,160.484 139.297,160.484 ; 139.007,160.499 139.312,160.499 ; 139.023,160.515 139.327,160.515 ; 139.038,160.53 139.343,160.53 ; 139.053,160.545 139.358,160.545 ; 139.068,160.56 139.373,160.56 ; 139.084,160.576 139.388,160.576 ; 139.099,160.591 139.404,160.591 ; 139.114,160.606 139.419,160.606 ; 139.129,160.621 139.434,160.621 ; 139.145,160.637 139.449,160.637 ; 139.16,160.652 139.465,160.652 ; 139.175,160.667 139.48,160.667 ; 139.19,160.682 139.495,160.682 ; 139.205,160.698 139.51,160.698 ; 139.221,160.713 139.526,160.713 ; 139.236,160.728 139.536,160.728 ; 139.251,160.743 139.543,160.743 ; 139.266,160.759 139.546,160.759 ; 139.282,160.774 139.548,160.774 ; 139.297,160.789 139.546,160.789 ; 139.312,160.804 139.541,160.804 ; 139.327,160.82 139.531,160.82 ; 139.343,160.835 139.52,160.835 ; 139.358,160.85 139.505,160.85 ; 139.373,160.865 139.49,160.865 ; 139.393,160.88 139.467,160.88 ; 138.418,159.905 138.426,159.92 ; 138.418,159.905 138.41,159.872 138.413,159.854 138.418,159.839 138.438,159.809 138.466,159.781 138.497,159.76 138.512,159.755 138.53,159.753 138.563,159.76 138.576,159.768 ; 138.426,159.92 138.436,159.933 139.383,160.875 139.396,160.883 139.429,160.891 139.447,160.888 139.462,160.883 139.492,160.863 139.52,160.835 ; 138.576,159.768 139.523,160.71 139.533,160.723 139.541,160.738 139.548,160.771 139.546,160.789 ; 139.52,160.835 139.541,160.804 ; 139.541,160.804 139.546,160.789
  Top Layer w0.241: 138.979,160.322 142.284,163.629 149.754,163.629 150.516,164.391
  Top Layer w0.635: 150.516,164.391 152.167,166.042 pad.1@152.167,168.455
$Net42: pad.1@154.707,168.455 | length 44.2
  Top Layer w0.03: 138.766,159.506 139.023,159.506 ; 138.766,159.522 139.038,159.522 ; 138.769,159.537 139.053,159.537 ; 138.771,159.491 139.007,159.491 ; 138.779,159.476 138.992,159.476 ; 138.789,159.461 138.977,159.461 ; 138.794,159.583 139.099,159.583 ; 138.802,159.445 138.962,159.445 ; 138.809,159.598 139.114,159.598 ; 138.817,159.43 138.946,159.43 ; 138.824,159.613 139.129,159.613 ; 138.84,159.415 138.929,159.415 ; 138.84,159.628 139.145,159.628 ; 138.855,159.643 139.16,159.643 ; 138.87,159.659 139.175,159.659 ; 138.885,159.674 139.19,159.674 ; 138.901,159.689 139.205,159.689 ; 138.916,159.704 139.221,159.704 ; 138.931,159.72 139.236,159.72 ; 138.946,159.735 139.251,159.735 ; 138.962,159.75 139.266,159.75 ; 138.977,159.765 139.282,159.765 ; 138.992,159.781 139.297,159.781 ; 139.007,159.796 139.312,159.796 ; 139.023,159.811 139.327,159.811 ; 139.038,159.826 139.343,159.826 ; 139.053,159.842 139.358,159.842 ; 139.068,159.552 138.771,159.552 ; 139.068,159.857 139.373,159.857 ; 139.084,159.567 138.779,159.567 ; 139.084,159.872 139.388,159.872 ; 139.099,159.887 139.406,159.887 ; 139.114,159.903 139.421,159.903 ; 139.129,159.918 139.437,159.918 ; 139.145,159.933 139.452,159.933 ; 139.16,159.948 139.467,159.948 ; 139.175,159.964 139.482,159.964 ; 139.19,159.979 139.498,159.979 ; 139.205,159.994 139.513,159.994 ; 139.221,160.009 139.528,160.009 ; 139.236,160.024 139.543,160.024 ; 139.251,160.04 139.559,160.04 ; 139.269,160.055 139.574,160.055 ; 139.284,160.07 139.589,160.07 ; 139.299,160.085 139.604,160.085 ; 139.315,160.101 139.619,160.101 ; 139.33,160.116 139.635,160.116 ; 139.345,160.131 139.65,160.131 ; 139.36,160.146 139.665,160.146 ; 139.376,160.162 139.68,160.162 ; 139.391,160.177 139.696,160.177 ; 139.406,160.192 139.711,160.192 ; 139.421,160.207 139.726,160.207 ; 139.437,160.223 139.741,160.223 ; 139.452,160.238 139.757,160.238 ; 139.467,160.253 139.772,160.253 ; 139.482,160.268 139.787,160.268 ; 139.498,160.284 139.802,160.284 ; 139.513,160.299 139.818,160.299 ; 139.528,160.314 139.833,160.314 ; 139.543,160.329 139.848,160.329 ; 139.559,160.345 139.863,160.345 ; 139.574,160.36 139.879,160.36 ; 139.589,160.375 139.889,160.375 ; 139.604,160.39 139.896,160.39 ; 139.619,160.405 139.899,160.405 ; 139.635,160.421 139.901,160.421 ; 139.65,160.436 139.899,160.436 ; 139.665,160.451 139.894,160.451 ; 139.68,160.466 139.884,160.466 ; 139.696,160.482 139.873,160.482 ; 139.711,160.497 139.858,160.497 ; 139.726,160.512 139.843,160.512 ; 139.746,160.527 139.82,160.527 ; 138.771,159.552 138.779,159.567 ; 138.771,159.552 138.764,159.519 138.766,159.501 138.771,159.486 138.791,159.456 138.819,159.428 138.85,159.407 138.865,159.402 138.883,159.4 138.916,159.407 138.929,159.415 ; 138.779,159.567 138.789,159.58 139.736,160.522 139.749,160.53 139.782,160.538 139.8,160.535 139.815,160.53 139.846,160.51 139.873,160.482 ; 138.929,159.415 139.876,160.357 139.886,160.37 139.894,160.385 139.901,160.418 139.899,160.436 ; 139.873,160.482 139.894,160.451 ; 139.894,160.451 139.899,160.436
  Top Layer w0.241: 139.332,159.969 142.485,163.121 151.786,163.121 152.548,163.883
  Top Layer w0.635: 152.548,163.883 154.707,166.042 pad.1@154.707,168.455
$Net43: pad.1@157.247,168.455 | length 46.5
  Top Layer w0.03: 139.119,159.153 139.376,159.153 ; 139.119,159.169 139.391,159.169 ; 139.122,159.184 139.406,159.184 ; 139.124,159.138 139.36,159.138 ; 139.132,159.123 139.345,159.123 ; 139.142,159.108 139.33,159.108 ; 139.147,159.229 139.452,159.229 ; 139.155,159.092 139.315,159.092 ; 139.162,159.245 139.467,159.245 ; 139.17,159.077 139.299,159.077 ; 139.178,159.26 139.482,159.26 ; 139.193,159.062 139.282,159.062 ; 139.193,159.275 139.498,159.275 ; 139.208,159.29 139.513,159.29 ; 139.223,159.306 139.528,159.306 ; 139.238,159.321 139.543,159.321 ; 139.254,159.336 139.559,159.336 ; 139.269,159.351 139.574,159.351 ; 139.284,159.367 139.589,159.367 ; 139.299,159.382 139.604,159.382 ; 139.315,159.397 139.619,159.397 ; 139.33,159.412 139.635,159.412 ; 139.345,159.428 139.65,159.428 ; 139.36,159.443 139.665,159.443 ; 139.376,159.458 139.68,159.458 ; 139.391,159.473 139.696,159.473 ; 139.406,159.489 139.711,159.489 ; 139.421,159.199 139.124,159.199 ; 139.421,159.504 139.726,159.504 ; 139.437,159.214 139.132,159.214 ; 139.437,159.519 139.741,159.519 ; 139.452,159.534 139.759,159.534 ; 139.467,159.55 139.774,159.55 ; 139.482,159.565 139.79,159.565 ; 139.498,159.58 139.805,159.58 ; 139.513,159.595 139.82,159.595 ; 139.528,159.61 139.835,159.61 ; 139.543,159.626 139.851,159.626 ; 139.559,159.641 139.866,159.641 ; 139.574,159.656 139.881,159.656 ; 139.589,159.671 139.896,159.671 ; 139.604,159.687 139.912,159.687 ; 139.622,159.702 139.927,159.702 ; 139.637,159.717 139.942,159.717 ; 139.653,159.732 139.957,159.732 ; 139.668,159.748 139.973,159.748 ; 139.683,159.763 139.988,159.763 ; 139.698,159.778 140.003,159.778 ; 139.713,159.793 140.018,159.793 ; 139.729,159.809 140.034,159.809 ; 139.744,159.824 140.049,159.824 ; 139.759,159.839 140.064,159.839 ; 139.774,159.854 140.079,159.854 ; 139.79,159.87 140.094,159.87 ; 139.805,159.885 140.11,159.885 ; 139.82,159.9 140.125,159.9 ; 139.835,159.915 140.14,159.915 ; 139.851,159.931 140.155,159.931 ; 139.866,159.946 140.171,159.946 ; 139.881,159.961 140.186,159.961 ; 139.896,159.976 140.201,159.976 ; 139.912,159.991 140.216,159.991 ; 139.927,160.007 140.232,160.007 ; 139.942,160.022 140.242,160.022 ; 139.957,160.037 140.249,160.037 ; 139.973,160.052 140.252,160.052 ; 139.988,160.068 140.254,160.068 ; 140.003,160.083 140.252,160.083 ; 140.018,160.098 140.247,160.098 ; 140.034,160.113 140.237,160.113 ; 140.049,160.129 140.227,160.129 ; 140.064,160.144 140.211,160.144 ; 140.079,160.159 140.196,160.159 ; 140.1,160.174 140.173,160.174 ; 139.124,159.199 139.132,159.214 ; 139.124,159.199 139.117,159.166 139.119,159.148 139.124,159.133 139.145,159.102 139.172,159.075 139.203,159.054 139.218,159.049 139.236,159.047 139.269,159.054 139.282,159.062 ; 139.132,159.214 139.142,159.227 140.089,160.169 140.102,160.177 140.135,160.185 140.153,160.182 140.168,160.177 140.199,160.157 140.227,160.129 ; 139.282,159.062 140.229,160.004 140.239,160.017 140.247,160.032 140.254,160.065 140.252,160.083 ; 140.227,160.129 140.247,160.098 ; 140.247,160.098 140.252,160.083
  Top Layer w0.241: 139.686,159.616 142.683,162.613 153.818,162.613 154.58,163.375
  Top Layer w0.635: 154.58,163.375 157.247,166.042 pad.1@157.247,168.455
